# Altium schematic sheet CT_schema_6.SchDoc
size 287 x 160 mm
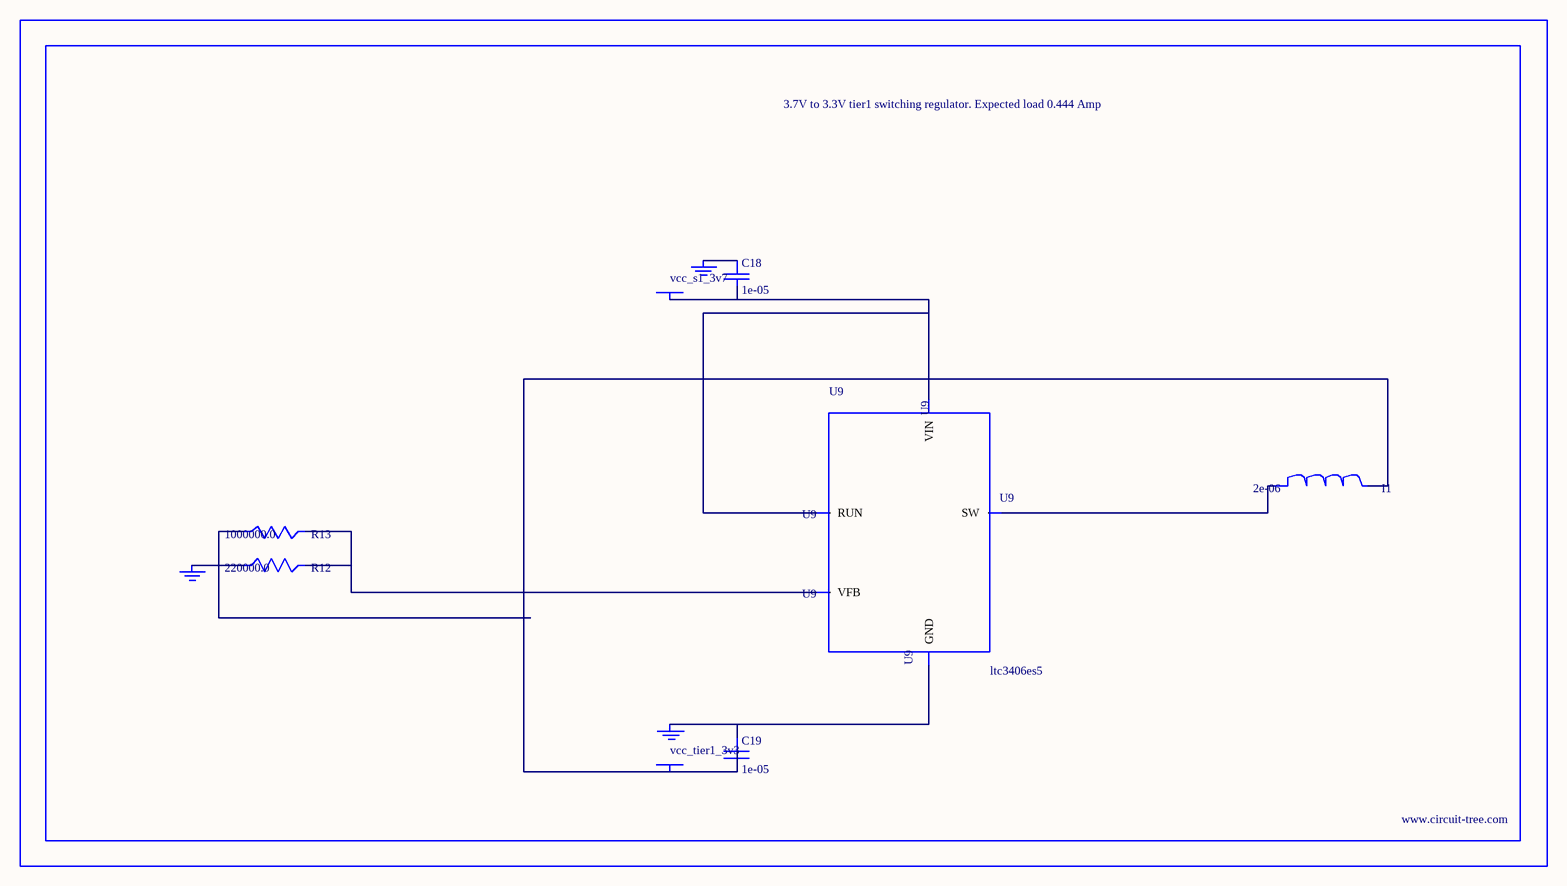
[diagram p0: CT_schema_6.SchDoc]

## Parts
BORDER5  (no value)
C18  1e-05  [C0805]
C19  1e-05  [C0805]
GND_INSTANCE_5_0  (no value)
GND_INSTANCE_5_1  (no value)
GND_INSTANCE_5_2  (no value)
I1  2e-06  [WE-HCI_7030/7040/7050]
POWER_INSTANCE_5_0  vcc_tier1_3v3
POWER_INSTANCE_5_1  vcc_s1_3v7
R12  220000.0  [R0603]
R13  1000000.0  [R0603]
U9  ltc3406es5  [TSOT-23-5]

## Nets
NetC18_1: C18.1 GND_INSTANCE_5_1.0(GND)
NetC18_2: C18.2 POWER_INSTANCE_5_1.0(PWR) U9.1(RUN) U9.4(VIN)
NetC19_1: C19.1 GND_INSTANCE_5_0.0(GND) U9.2(GND)
NetC19_2: C19.2 I1.2 POWER_INSTANCE_5_0.0(PWR) R13.1
NetGND_INSTANCE_5_2_0: GND_INSTANCE_5_2.0(GND) R12.1
NetI1_1: I1.1 U9.3(SW)
NetR12_2: R12.2 R13.2 U9.5(VFB)

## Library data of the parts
BORDER5 = BORDER_PAGE5
C18 C19 = C0805C106K8RACTU
GND_INSTANCE_5_0-GND_INSTANCE_5_2 = GND
I1 = 744314200
POWER_INSTANCE_5_0 POWER_INSTANCE_5_1 = PWR
R12 = RC0603JR-07220KL
R13 = RC0603JR-071ML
